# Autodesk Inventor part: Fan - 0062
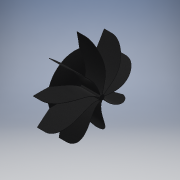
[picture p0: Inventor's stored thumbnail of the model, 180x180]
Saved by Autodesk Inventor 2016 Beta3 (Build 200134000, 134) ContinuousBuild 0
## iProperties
Created: 2006-05
Part Number: Fan - 0062
Document SubType Name: Modeling
Designer: Autodesk, Inc.
Density: 1 g/cm^3
Description: Propeller Fan -  0062
Mass: 1278.83 g
Surface Area: 8884.25 cm^2
Volume: 1278.83 cm^3
Material: Generic
Appearance: Black Cast
Author: Autodesk, Inc.
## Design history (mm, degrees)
sketch "Sketch1"
  geometry: L1 (-343.436, 0)-(311.024, 0) reference; L2 (170, 18)-(0, 18); L3 (0, 18)-(0, 275); L4 (0, 275)-(50, 275); L5 (50, 275)-(170, 18); L6 (170, 18)-(174.823, 0); L7 (0, 18)-(170, 18); L8 (170, 18)-(170, 15); L9 (170, 15)-(0, 15); L10 (0, 15)-(0, 18); A1 r 300 centre (-249.942, 12.081) between (50, 18) and (0, 178); 2 further points
  constraints: 18 end point, 4 parallel, 4 point on line, 2 horizontal, 2 perpendicular, 2 point on circle, 1 centre point, 4 other
  dimensions: "d0" = 75 deg angle of L1 L6; "d2" = 550 diameter of L4 L1; "d3" = 50 distance of L2.end A1.start; "d4" = 50 distance of L3.end L4.end; "d5" = 160 distance from line of L3 point (160, 156.705); "d6" = 170 distance of L2.start L2.end; "d7" = 160 distance from line of L2 A1.end; "d8" = 300 radius of A1; "d9" = 3 distance between parallel lines of L2 L9; "d10" = 30 diameter of L9 L1
sketch "Sketch2"
  geometry: L1 (18, 0)-(275, 0) reference; L2 (15, 0)-(18, 0) reference; L3 (15.513, 1.41)-(14.487, -1.41); L4 (275.969, 36.421)-(274.943, 39.24); L5 (275.969, 36.421)-(516.026, 123.795); L6 (516.026, 123.795)-(515, 126.614); L7 (515, 126.614)-(274.943, 39.24); L8 (15.513, 1.41)-(12.694, 2.436); L9 (12.694, 2.436)-(11.668, -0.383); L10 (11.668, -0.383)-(14.487, -1.41); L11 (515, 126.614)-(15, 126.614); L12 (15, 126.614)-(15, 0)
  constraints: 20 end point, 5 perpendicular, 3 equal length, 2 parallel, 1 midpoint, 1 vertical, 8 other
  dimensions: "d15" = 3 distance of L4.start L4.end; "d16" = 500 distance of L6.end L11.end; "d17" = 20 deg angle of L11 L7; "d18" = 20 deg angle of L11 L8
extrude "Extrusion1" new body sketch "Sketch1" stored distance "d19" = 100; taper "d20" = 0 deg
extrude "Extrusion2" sketch "Sketch2" distance "d21" = 300; taper "d22" = 0 deg
pattern_circular "Circular Pattern1" dims "d24" = 360 deg
feature "RevolutionSrf1" dims angle "d11" = 90 deg
thicken "Thicken1" dims "d12" = 3, "d13" = 3
revolve "Revolution1" stored, may be unused: angle "d14" = 90 deg
thicken "Thicken2" dims "d26" = 3, "d27" = 3
sketch "Sketch3"
  geometry: A1 r 18 centre (0, 0) between (0, 18) and (-11.57, 13.789) reference; A2 r 18 centre (0, 0) between (-11.57, 13.789) and (-17.727, 3.126) reference; A3 r 18 centre (0, 0) between (-17.727, 3.126) and (-15.588, -9) reference; A4 r 18 centre (0, 0) between (-15.588, -9) and (-6.156, -16.914) reference; A5 r 18 centre (0, 0) between (-6.156, -16.914) and (6.156, -16.914) reference; A6 r 18 centre (0, 0) between (6.156, -16.914) and (15.588, -9) reference; A7 r 18 centre (0, 0) between (15.588, -9) and (17.727, 3.126) reference; A8 r 18 centre (0, 0) between (17.727, 3.126) and (11.57, 13.789) reference; A9 r 18 centre (0, 0) between (11.57, 13.789) and (0, 18) reference
extrude "Extrusion3" join sketch "Sketch3" distance "d28" = 2; taper "d29" = 0 deg
fillet "Fillet1" dims "d30" = 2
body "Solid1"
body "Srf1"
